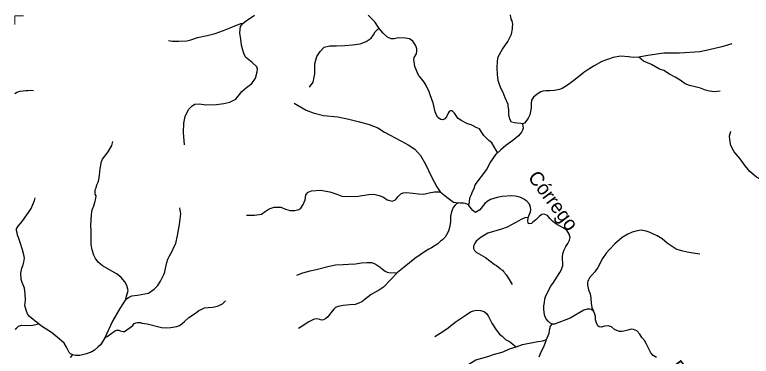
# Model space of a CAD drawing. Extents: x 436.3 to 500.4, y 8231 to 8286.4.
# Drawn here: x 446.37 to 456.78, y 8281.47 to 8286.3 of the extents above; entities that cross this region are included whole.
import ezdxf
from ezdxf.enums import TextEntityAlignment as Align

# ---------------------------------------------------------------- set-up
doc = ezdxf.new("R2010")
doc.units = 0
doc.header["$LTSCALE"] = 0.08
doc.linetypes.add('LONG_DASHED', pattern=[7.5, 6, -1.5])
doc.layers.add('61', color=7, linetype='Continuous')
for name, color, linetype, lineweight in [('63', 7, 'Continuous', 13), ('7', 7, 'Continuous', 25), ('9', 7, 'LONG_DASHED', 25)]:
    doc.layers.add(name, color=color, linetype=linetype, lineweight=lineweight)

msp = doc.modelspace()

# ---------------------------------------------------------------- linework, layer by layer
at = {"layer": '63'}
msp.add_lwpolyline([(446.4936, 8286.2876), (446.3704, 8286.2876), (446.3704, 8286.1662)], dxfattribs=at)
at = {"layer": '7'}
for points in [[(451.5229, 8286.1066), (451.5139, 8286.1243), (451.4687, 8286.1905), (451.4551, 8286.2082), (451.3698, 8286.294), (451.3642, 8286.2987)], [(453.1758, 8284.3305), (453.1874, 8284.344), (453.1874, 8284.3632), (453.1816, 8284.3805), (453.1163, 8284.4922), (453.0693, 8284.5228), (453.0241, 8284.572), (453.0015, 8284.5944), (452.9744, 8284.639), (452.9383, 8284.6882), (452.8931, 8284.7106), (452.8525, 8284.7329), (452.8209, 8284.7464), (452.7713, 8284.7598), (452.681, 8284.8091), (452.6313, 8284.8403), (452.6041, 8284.8849), (452.5858, 8284.9121), (452.554, 8284.9435), (452.5275, 8284.9436), (452.5117, 8284.9331), (452.4959, 8284.9123), (452.4748, 8284.8602), (452.4484, 8284.8289), (452.4193, 8284.8185), (452.3922, 8284.823), (452.3696, 8284.8364), (452.3515, 8284.8498), (452.3334, 8284.881), (452.3107, 8284.93), (452.2833, 8285.0591), (452.2652, 8285.1036), (452.2379, 8285.1837), (452.2288, 8285.2193), (452.2061, 8285.2593), (452.1835, 8285.3038), (452.1563, 8285.3482), (452.1246, 8285.3927), (452.0793, 8285.4505), (452.0253, 8285.573), (452.0093, 8285.6717), (452.0157, 8285.6989), (452.0472, 8285.7521), (452.0516, 8285.7919), (452.0516, 8285.8229), (452.038, 8285.8628), (452.0355, 8285.8741), (451.9982, 8285.9312), (451.9505, 8285.9624), (451.8923, 8285.9728), (451.7917, 8285.978), (451.7334, 8285.9626), (451.6911, 8285.9626), (451.638, 8285.9834), (451.5798, 8286.0404), (451.5229, 8286.1066)], [(452.7863, 8283.6157), (452.7998, 8283.647), (452.7998, 8283.6739), (452.8088, 8283.7231), (452.8268, 8283.7634), (452.8403, 8283.8037), (452.8628, 8283.8484), (452.8807, 8283.8962), (453.0428, 8284.1164), (453.0653, 8284.1655), (453.0902, 8284.2115), (453.1758, 8284.3305)], [(453.629, 8283.4344), (453.6605, 8283.515), (453.665, 8283.5464), (453.6605, 8283.5822), (453.647, 8283.6271), (453.6064, 8283.6675), (453.5658, 8283.6945), (453.5253, 8283.7169), (453.4892, 8283.7305), (453.4442, 8283.7395), (453.3946, 8283.7441), (453.2595, 8283.731), (453.2144, 8283.7222), (453.1874, 8283.7177), (453.0973, 8283.6911), (453.0477, 8283.6643), (453.0162, 8283.633), (452.945, 8283.5451), (452.8828, 8283.5067), (452.8673, 8283.5144), (452.8478, 8283.5375), (452.8207, 8283.5647), (452.7863, 8283.6157)], [(453.967, 8281.9264), (453.9359, 8281.9458), (453.9088, 8281.973), (453.8776, 8282.008), (453.8582, 8282.0622), (453.8499, 8282.1403), (453.8499, 8282.1897), (453.8589, 8282.2347), (453.8634, 8282.2842), (453.8724, 8282.3156), (453.8905, 8282.356), (453.913, 8282.401), (453.9445, 8282.4593), (453.9783, 8282.5048), (454.0751, 8282.6613), (454.0976, 8282.7017), (454.1156, 8282.7601), (454.1156, 8282.796), (454.1111, 8282.841), (454.1111, 8282.8904), (454.1201, 8282.9398), (454.1381, 8282.9801), (454.1606, 8283.025), (454.1879, 8283.0691), (454.2111, 8283.1155), (454.2189, 8283.1541), (454.2073, 8283.2005), (454.1722, 8283.2585), (454.1141, 8283.2973), (454.0209, 8283.3476), (453.9703, 8283.3864), (453.9354, 8283.4212), (453.9005, 8283.4638), (453.8538, 8283.4851), (453.8228, 8283.4774), (453.7879, 8283.4544), (453.7375, 8283.4042), (453.6947, 8283.3696), (453.6753, 8283.3504), (453.6314, 8283.345), (453.6246, 8283.3851), (453.629, 8283.4344)], [(454.5492, 8282.1112), (454.5221, 8282.1345), (454.4988, 8282.1423), (454.4638, 8282.1424), (454.4134, 8282.127), (454.2193, 8282.015), (453.998, 8281.9302), (453.967, 8281.9264)], [(455.4435, 8281.4581), (455.394, 8281.4852), (455.3625, 8281.5212), (455.295, 8281.6563), (455.2725, 8281.6969), (455.2365, 8281.7419), (455.205, 8281.787), (455.1645, 8281.8365), (455.115, 8281.8546), (455.0835, 8281.8592), (455.034, 8281.8457), (454.98, 8281.8278), (454.953, 8281.8233), (454.917, 8281.8234), (454.881, 8281.8369), (454.8495, 8281.855), (454.8045, 8281.8911), (454.7595, 8281.9046), (454.7099, 8281.9002), (454.6604, 8281.8868), (454.6334, 8281.8913), (454.6109, 8281.9049), (454.5919, 8281.9484), (454.5803, 8281.9911), (454.5803, 8282.0376), (454.5686, 8282.0686), (454.5492, 8282.1112)]]:
    msp.add_lwpolyline(points, dxfattribs=at)
at = {"layer": '9'}
for points in [[(449.596, 8286.1809), (449.6486, 8286.2196), (449.7388, 8286.2803), (449.7572, 8286.2952)], [(453.5493, 8284.7589), (453.5218, 8284.765), (453.4729, 8284.7711), (453.4362, 8284.7741), (453.3934, 8284.7863), (453.3689, 8284.8286), (453.3566, 8284.886), (453.3525, 8284.9643), (453.3463, 8285.0126), (453.3432, 8285.0337), (453.3003, 8285.1272), (453.2757, 8285.2056), (453.242, 8285.2659), (453.2205, 8285.3171), (453.205, 8285.3714), (453.1926, 8285.4588), (453.1895, 8285.552), (453.1923, 8285.6483), (453.2039, 8285.7097), (453.2638, 8285.814), (453.3421, 8285.9233), (453.3942, 8286.0262), (453.4072, 8286.1034), (453.4081, 8286.1258), (453.409, 8286.1684), (453.4021, 8286.2153), (453.3888, 8286.2391), (453.3815, 8286.2717), (453.3788, 8286.2933), (453.3788, 8286.3029)], [(448.544, 8285.9373), (448.6022, 8285.9278), (448.6918, 8285.9311), (448.8039, 8285.9341), (448.8577, 8285.9466), (448.9519, 8285.9804), (449.0908, 8286.01), (449.2031, 8286.0395), (449.32, 8286.0823), (449.4145, 8286.1165), (449.5044, 8286.1552), (449.5319, 8286.1655), (449.5644, 8286.1776), (449.596, 8286.1809)], [(448.7696, 8284.4628), (448.7552, 8284.6383), (448.7627, 8284.7697), (448.7775, 8284.8642), (448.8287, 8284.9653), (448.8798, 8285.0156), (448.9163, 8285.0368), (448.982, 8285.0433), (449.0696, 8285.0279), (449.223, 8285.0335), (449.3253, 8285.047), (449.4131, 8285.0678), (449.4936, 8285.1104), (449.5815, 8285.2177), (449.6474, 8285.2747), (449.7205, 8285.3317), (449.7738, 8285.4069), (449.7964, 8285.4949), (449.8009, 8285.5346), (449.7919, 8285.5655), (449.7244, 8285.6277), (449.6345, 8285.7031), (449.612, 8285.7473), (449.5941, 8285.8), (449.5763, 8285.8747), (449.5674, 8285.9579), (449.5532, 8286.041), (449.5547, 8286.0936), (449.5625, 8286.1356), (449.596, 8286.1809)], [(450.5364, 8285.2791), (450.5879, 8285.351), (450.61, 8285.4662), (450.6117, 8285.6066), (450.6382, 8285.7101), (450.6859, 8285.7825), (450.7441, 8285.8443), (450.8236, 8285.8648), (450.919, 8285.8646), (451.0355, 8285.8695), (451.1467, 8285.8796), (451.2527, 8285.8898), (451.3374, 8285.9259), (451.4063, 8285.9724), (451.4433, 8286.019), (451.4644, 8286.0603), (451.4856, 8286.081), (451.5015, 8286.0965), (451.5229, 8286.1066)], [(456.5075, 8285.8926), (456.3642, 8285.8471), (456.1874, 8285.8076), (456.0562, 8285.7803), (455.7665, 8285.7587), (455.5468, 8285.7584), (455.318, 8285.725), (455.1899, 8285.7008)], [(455.1899, 8285.7008), (455.1117, 8285.6975), (455.0476, 8285.7096), (454.9377, 8285.7186), (454.8309, 8285.6974), (454.6693, 8285.6431), (454.5626, 8285.5828), (454.4833, 8285.5315), (454.4131, 8285.4863), (454.2912, 8285.3868), (454.1988, 8285.3165), (454.1469, 8285.2834), (454.1103, 8285.2623), (454.0707, 8285.2442), (453.9975, 8285.2322), (453.9333, 8285.2292), (453.8752, 8285.2292), (453.8356, 8285.2233), (453.8051, 8285.2113), (453.7532, 8285.1781), (453.7044, 8285.136), (453.677, 8285.0937), (453.6679, 8285.0424), (453.668, 8284.9851), (453.6589, 8284.9338), (453.6499, 8284.8856), (453.6285, 8284.8403), (453.6072, 8284.8101), (453.5737, 8284.7709), (453.5493, 8284.7589)], [(456.3396, 8285.22), (456.2552, 8285.2136), (456.1926, 8285.2229), (456.1331, 8285.2383), (456.0641, 8285.263), (455.989, 8285.2847), (455.9076, 8285.3033), (455.8451, 8285.3249), (455.7761, 8285.3775), (455.7041, 8285.4209), (455.6258, 8285.461), (455.5444, 8285.5136), (455.4848, 8285.5352), (455.372, 8285.5971), (455.2562, 8285.6466), (455.1899, 8285.7008)], [(446.6346, 8285.2283), (446.5869, 8285.2298), (446.5572, 8285.2273), (446.5251, 8285.226), (446.4877, 8285.2222), (446.4438, 8285.2156), (446.4116, 8285.2077), (446.3948, 8285.1999), (446.3729, 8285.1837)], [(450.3202, 8285.0541), (450.4899, 8284.9543), (450.5907, 8284.9173), (450.7339, 8284.8803), (450.9356, 8284.8587), (451.0947, 8284.8268), (451.2433, 8284.7899), (451.3813, 8284.753), (451.5034, 8284.7058), (451.599, 8284.6429), (451.8272, 8284.5223), (451.9337, 8284.4621), (452.024, 8284.4044), (452.1036, 8284.3152), (452.178, 8284.1895), (452.263, 8284.0112), (452.3372, 8283.8695), (452.3836, 8283.8003)], [(453.5493, 8284.7589), (453.5551, 8284.699), (453.547, 8284.6696), (453.5343, 8284.643), (453.4887, 8284.5914), (453.4104, 8284.5269), (453.3123, 8284.4559), (453.2405, 8284.3913), (453.1758, 8284.3305)], [(456.5392, 8284.3663), (456.4901, 8284.4566), (456.4772, 8284.5331), (456.4729, 8284.5894), (456.49, 8284.6581)], [(447.61, 8284.2629), (447.6902, 8284.3655), (447.7416, 8284.4558), (447.7576, 8284.51)], [(457.3107, 8283.7684), (457.2632, 8283.8112), (457.2252, 8283.8407), (457.1235, 8283.887), (457.0177, 8283.9163), (456.8569, 8284.0088), (456.7595, 8284.0845), (456.6959, 8284.1645), (456.6239, 8284.2654), (456.5392, 8284.3663)], [(447.9404, 8282.2816), (447.9499, 8282.3234), (447.9715, 8282.404), (447.9567, 8282.4775), (447.9274, 8282.5288), (447.8762, 8282.5876), (447.8177, 8282.6354), (447.6131, 8282.7552), (447.5512, 8282.8066), (447.5111, 8282.8582), (447.4892, 8282.9024), (447.4635, 8282.9797), (447.4525, 8283.0532), (447.4486, 8283.1748), (447.4521, 8283.2558), (447.4483, 8283.3185), (447.4518, 8283.3996), (447.4553, 8283.4808), (447.4658, 8283.5449), (447.4875, 8283.6002), (447.5054, 8283.6667), (447.5162, 8283.7073), (447.5198, 8283.7443), (447.5089, 8283.7666), (447.5052, 8283.7962), (447.5088, 8283.8258), (447.5197, 8283.8553), (447.5304, 8283.896), (447.5485, 8283.9367), (447.5594, 8283.97), (447.5665, 8284.033), (447.5774, 8284.1294), (447.5955, 8284.2295), (447.61, 8284.2629)], [(449.6477, 8283.4674), (449.7589, 8283.4673), (449.8595, 8283.4832), (449.9125, 8283.52), (449.9653, 8283.5569), (450.0395, 8283.5831), (450.1297, 8283.583), (450.1987, 8283.5566), (450.2623, 8283.5355), (450.3313, 8283.5354), (450.3843, 8283.5511), (450.4162, 8283.5669), (450.4479, 8283.6194), (450.4743, 8283.6878), (450.4849, 8283.7562), (450.5166, 8283.793), (450.5644, 8283.8139), (450.6917, 8283.8242), (450.8245, 8283.7978), (450.9253, 8283.766), (450.9944, 8283.7397), (451.0952, 8283.7343), (451.2226, 8283.7394), (451.3712, 8283.7602), (451.4455, 8283.7653), (451.5198, 8283.7495), (451.5834, 8283.7232), (451.6365, 8283.6863), (451.7055, 8283.6652), (451.7532, 8283.6861), (451.7903, 8283.7334), (451.8275, 8283.77), (451.8592, 8283.7857), (451.907, 8283.7909), (451.9971, 8283.7802), (452.0765, 8283.7696), (452.1507, 8283.7642), (452.2301, 8283.785), (452.3043, 8283.8005), (452.3836, 8283.8003)], [(446.7081, 8281.9341), (446.5815, 8282.0376), (446.55, 8282.0758), (446.5311, 8282.1269), (446.5154, 8282.1906), (446.5217, 8282.267), (446.5187, 8282.3594), (446.5092, 8282.4392), (446.4777, 8282.519), (446.462, 8282.5605), (446.4589, 8282.6512), (446.4715, 8282.7214), (446.4905, 8282.766), (446.4999, 8282.8043), (446.5063, 8282.8618), (446.4971, 8282.9096), (446.4814, 8282.9799), (446.4469, 8283.0822), (446.4249, 8283.1527), (446.4092, 8283.1879), (446.4061, 8283.2199), (446.3935, 8283.2519), (446.3967, 8283.2775), (446.4188, 8283.3159), (446.4758, 8283.3782), (446.52, 8283.439), (446.564, 8283.5063), (446.6018, 8283.5639), (446.649, 8283.6763), (446.6585, 8283.7148)], [(452.3836, 8283.8003), (452.4802, 8283.7223), (452.5701, 8283.6537), (452.6442, 8283.6431)], [(452.6442, 8283.6431), (452.6164, 8283.6305), (452.595, 8283.6093), (452.5698, 8283.5759), (452.5518, 8283.54), (452.5423, 8283.5156), (452.5316, 8283.4544), (452.5289, 8283.3771), (452.5154, 8283.2945), (452.4994, 8283.2413), (452.4725, 8283.1906), (452.4537, 8283.1586), (452.4165, 8283.123), (452.3894, 8283.1006), (452.3487, 8283.0647), (452.263, 8283.0065), (452.2223, 8282.9886), (452.1772, 8282.9617), (452.0268, 8282.8582), (451.8763, 8282.7356), (451.78, 8282.6592)], [(452.7863, 8283.6157), (452.7412, 8283.6337), (452.7141, 8283.6383), (452.6647, 8283.6411), (452.6442, 8283.6431)], [(447.9404, 8282.2816), (447.9807, 8282.3048), (448.0254, 8282.3273), (448.106, 8282.3362), (448.263, 8282.3677), (448.339, 8282.4241), (448.3928, 8282.4737), (448.4329, 8282.5368), (448.4771, 8282.6286), (448.4904, 8282.6692), (448.4992, 8282.7143), (448.5125, 8282.7594), (448.5213, 8282.8), (448.5346, 8282.8451), (448.5524, 8282.8856), (448.6015, 8282.9714), (448.62, 8283.0148), (448.6468, 8283.0689), (448.6733, 8283.1817), (448.6998, 8283.3397), (448.7196, 8283.4887), (448.7057, 8283.5718)], [(453.629, 8283.4344), (453.5815, 8283.4304), (453.5403, 8283.4133), (453.3306, 8283.2976), (453.2515, 8283.2705), (453.0589, 8283.2162), (452.9625, 8283.1583), (452.8937, 8283.1001), (452.8675, 8283.0637), (452.863, 8283.0502), (452.854, 8283.0323), (452.854, 8282.9964), (452.8675, 8282.9694), (452.881, 8282.9559), (452.8937, 8282.9462), (453.0244, 8282.8705), (453.147, 8282.7756), (453.1605, 8282.7666), (453.1786, 8282.7576), (453.2327, 8282.717), (453.2462, 8282.7035), (453.2642, 8282.69), (453.2777, 8282.672), (453.2913, 8282.6585), (453.3048, 8282.6405), (453.3183, 8282.627), (453.3272, 8282.613), (453.3588, 8282.5595), (453.3859, 8282.5144), (453.3994, 8282.4894)], [(456.0555, 8282.9181), (455.9896, 8282.9283), (455.9311, 8282.9359), (455.8727, 8282.9486), (455.7965, 8282.9664), (455.7202, 8282.9892), (455.6643, 8283.0273), (455.5907, 8283.0754), (455.5195, 8283.1362), (455.4509, 8283.1767), (455.3899, 8283.2072), (455.3391, 8283.23), (455.2934, 8283.2427), (455.2248, 8283.2554), (455.1703, 8283.2483), (455.0991, 8283.2281), (455.0383, 8283.2029), (454.9569, 8283.1549), (454.8528, 8283.0638), (454.774, 8282.9804), (454.7308, 8282.9323), (454.68, 8282.8564), (454.6128, 8282.7314), (454.5722, 8282.6706), (454.5315, 8282.625), (454.4959, 8282.582), (454.4807, 8282.5567), (454.4731, 8282.539), (454.468, 8282.5111), (454.468, 8282.4832), (454.4807, 8282.4122), (454.5037, 8282.3589), (454.5138, 8282.2942), (454.5189, 8282.2231), (454.529, 8282.1623), (454.5492, 8282.1112)], [(450.3575, 8282.6218), (450.442, 8282.6556), (450.5456, 8282.6808), (450.6493, 8282.704), (450.8164, 8282.7482), (450.9031, 8282.7671), (451.011, 8282.7734), (451.0873, 8282.7776), (451.1867, 8282.7817), (451.2735, 8282.7943), (451.3539, 8282.8006), (451.411, 8282.8006), (451.4512, 8282.7879), (451.4956, 8282.7648), (451.5359, 8282.7353), (451.5698, 8282.7059), (451.6057, 8282.6763), (451.6354, 8282.6616), (451.684, 8282.6553), (451.78, 8282.6592)], [(451.78, 8282.6592), (451.5808, 8282.4525), (451.5271, 8282.4151), (451.4061, 8282.3496), (451.3229, 8282.2828), (451.2772, 8282.2427), (451.2343, 8282.224), (451.1806, 8282.2079), (451.1053, 8282.1999), (451.0139, 8282.1919), (450.9441, 8282.1785), (450.9038, 8282.1625), (450.881, 8282.1393), (450.8404, 8282.0897), (450.7965, 8282.0314), (450.7682, 8282.0087), (450.7348, 8281.9898), (450.7053, 8281.9844), (450.6811, 8281.9925), (450.6623, 8282.0005), (450.63, 8282.0032), (450.5951, 8281.9925), (450.52, 8281.9576), (450.4556, 8281.9121), (450.3833, 8281.8666)], [(447.9404, 8282.2816), (447.8556, 8282.1511), (447.75, 8281.9694), (447.6452, 8281.7369)], [(447.6452, 8281.7369), (447.6776, 8281.7565), (447.7823, 8281.8313), (447.8103, 8281.843), (447.8405, 8281.8454), (447.8592, 8281.836), (447.8802, 8281.8289), (447.9035, 8281.8242), (447.9199, 8281.8266), (447.9547, 8281.8476), (448.0036, 8281.8804), (448.0385, 8281.9108), (448.0594, 8281.9366), (448.0804, 8281.9483), (448.0991, 8281.9507), (448.148, 8281.9506), (448.1691, 8281.9435), (448.2438, 8281.9342), (448.4472, 8281.8827), (448.5196, 8281.8757), (448.578, 8281.8828), (448.6621, 8281.8969), (448.6972, 8281.9087), (448.7322, 8281.9344), (448.7696, 8281.9649), (448.8325, 8282.0235), (448.9236, 8282.0844), (448.9727, 8282.122), (449.0077, 8282.136), (449.0521, 8282.1572), (449.1036, 8282.1642), (449.1692, 8282.169), (449.2372, 8282.1808), (449.3086, 8282.216), (449.3483, 8282.2582)], [(452.3104, 8281.7527), (452.4219, 8281.8267), (452.4962, 8281.876), (452.5954, 8281.956), (452.7502, 8282.0608), (452.8107, 8282.1015), (452.854, 8282.1149), (452.8973, 8282.1256), (452.954, 8282.1228), (453.0041, 8282.1096), (453.0413, 8282.0726), (453.066, 8282.0355), (453.1155, 8281.9429), (453.1774, 8281.8501), (453.2208, 8281.7884), (453.2578, 8281.7574), (453.3074, 8281.7141), (453.3631, 8281.6832), (453.4572, 8281.61)], [(446.3784, 8281.8594), (446.3961, 8281.8719), (446.425, 8281.9009), (446.465, 8281.9134), (446.5371, 8281.9077), (446.6214, 8281.916), (446.67, 8281.9229), (446.7081, 8281.9341)], [(447.1896, 8281.4935), (447.161, 8281.5094), (447.1389, 8281.5286), (447.104, 8281.6018), (447.0692, 8281.6623), (446.9965, 8281.7229), (446.889, 8281.809), (446.7626, 8281.892), (446.7081, 8281.9341)], [(453.889, 8281.714), (453.9257, 8281.7997), (453.933, 8281.8691), (453.944, 8281.8982), (453.967, 8281.9264)], [(447.6452, 8281.7369), (447.6164, 8281.6901), (447.5849, 8281.6361), (447.5469, 8281.6012), (447.4964, 8281.5631), (447.4584, 8281.5376), (447.3825, 8281.5091), (447.2908, 8281.487), (447.2306, 8281.4839), (447.1896, 8281.4935)], [(453.4572, 8281.61), (453.5487, 8281.6395), (453.7653, 8281.6824), (453.8333, 8281.6946), (453.889, 8281.714)], [(453.7827, 8281.4656), (453.8084, 8281.5279), (453.8487, 8281.6082), (453.889, 8281.714)], [(452.7874, 8281.3631), (452.8865, 8281.4246), (453.0598, 8281.4738), (453.1526, 8281.5045), (453.2578, 8281.5351), (453.3755, 8281.5843), (453.4572, 8281.61)], [(447.1601, 8281.4558), (447.1896, 8281.4935)]]:
    msp.add_lwpolyline(points, dxfattribs=at)

# ---------------------------------------------------------------- texts
at = {"layer": '61'}
msp.add_text('Córrego                                Panela', height=0.2, rotation=306.719, dxfattribs=at).set_placement((454.8629, 8282.3294), align=Align.CENTER)

doc.saveas('drawing.dxf')
